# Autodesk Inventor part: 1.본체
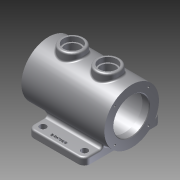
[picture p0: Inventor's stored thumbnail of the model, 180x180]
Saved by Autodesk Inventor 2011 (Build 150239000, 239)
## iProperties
Created: 2014-12
Part Number: 1.본체
Document SubType Name: Modeling
Designer: user
Density: 1 g/cm^3
Mass: 477.297 g
Surface Area: 1040.31 cm^2
Volume: 477.297 cm^3
Author: user
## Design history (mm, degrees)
sketch "스케치1"
  geometry: L1 (-47.5, 65)-(47.5, 65); L2 (47.5, 65)-(47.5, -65); L3 (47.5, -65)-(-47.5, -65); L4 (-47.5, -65)-(-47.5, 65); 3 further points
  constraints: 8 end point, 2 midpoint, 2 parallel, 1 horizontal, 1 horizontal alignment, 1 perpendicular, 1 vertical alignment
  dimensions: "d0" = 95 distance of L1.start L1.end; "d1" = 130 distance of L3.end L1.start
extrude "돌출1" new body sketch "스케치1" distance "d2" = 12; taper "d3" = 0 deg
node "작업 평면1"
sketch "스케치2"
  geometry: L1 (0, 130)-(0, 0) reference; C1 r 46 at (-50, 65); 1 further point
  constraints: 1 centre point, 1 horizontal alignment
  dimensions: "d5" = 92 diameter of C1; "d6" = 50 distance from line of L1 C1.centre
extrude "돌출2" join sketch "스케치2" distance "d7" = 140; taper "d8" = 0 deg
sketch "스케치3"
  geometry: L1 (-47.5, 4)-(-62.5, 4) reference; L2 (-62.5, 4)-(-62.5, 96) reference; L3 (-62.5, 96)-(77.5, 96) reference; L4 (77.5, 96)-(77.5, 4) reference; L5 (77.5, 4)-(47.5, 4) reference; L6 (47.5, 4)-(47.5, 0) reference; L7 (47.5, 0)-(-47.5, 0) reference; L8 (-47.5, 0)-(-47.5, 4) reference; L9 (77.5, 50)-(-62.5, 50); L10 (77.5, 80)-(65.5, 80); L11 (65.5, 80)-(65.5, 87.5); L12 (65.5, 87.5)-(-50.5, 87.5); L13 (-50.5, 87.5)-(-50.5, 80); L14 (-50.5, 80)-(-62.5, 80); 1 further point
  constraints: 12 end point, 3 parallel, 3 perpendicular, 2 midpoint, 2 point on line, 1 collinear
  dimensions: "d9" = 50 distance between parallel lines of L7 L9; "d10" = 60 diameter of L10 L9; "d11" = 60 diameter of L14 L9; "d12" = 75 diameter of L12 L9; "d13" = 12 distance of L10.start L10.end
revolve "회전1" sketch "스케치3" stored, may be unused: angle "d14" = 90 deg
sketch "스케치4"
  geometry: L1 (0, 0)-(0, 71.958); L2 (0, 0)-(-56.569, 56.569); C1 r 30 at (0, 0) reference; C2 r 46 at (0, 0) reference; 2 further points
  constraints: 4 end point, 1 midpoint, 1 vertical
  dimensions: "d16" = 45 deg angle of L1 L2; "d17" = 40 distance of C1.centre point (-28.284, 28.284)
hole "Hole1" sketch "스케치4" at (-28.284, 28.284) diameter "d18" = 3.242; stored, may be unused: countersink angle "d22" = 90 deg, drill point angle "d24" = 118 deg; dims "d19" = 8, "d20" = 4, "d21" = 2, "d23" = 10
sketch "스케치5"
  geometry: L1 (0, 0)-(0, -75.038); L2 (0, 0)-(50.786, -50.786); C1 r 30 at (0, 0) reference; C2 r 46 at (0, 0) reference; 2 further points
  constraints: 4 end point, 1 point on line, 1 vertical
  dimensions: "d28" = 45 deg angle of L1 L2; "d29" = 40 distance of C1.centre point (28.284, -28.284)
hole "Hole2" sketch "스케치5" at (28.284, -28.284) diameter "d30" = 3.242; stored, may be unused: countersink angle "d34" = 90 deg, drill point angle "d36" = 118 deg; dims "d31" = 8, "d32" = 4, "d33" = 2, "d35" = 10
node "작업 평면2"
sketch "스케치6"
  geometry: L1 (-37.5, 0)-(22.5, 0); L2 (-77.5, -46)-(-77.5, 46) reference; C1 r 20 at (-37.5, 0); C2 r 20 at (22.5, 0); 1 further point
  constraints: 2 centre point, 2 end point, 1 equal radius, 1 horizontal
  dimensions: "d41" = 60 distance of L1.start L1.end; "d42" = 40 diameter of C1; "d43" = 40 distance from line of L2 L1.start; "d44" = 46 vertical distance of L2.start L1.start
extrude "돌출3" join sketch "스케치6" stored distance "d45" = 8; taper "d46" = 0 deg
sketch "스케치7"
  geometry: C1 r 20 at (0, 0) reference; C2 r 15 at (0, 0); 1 further point
  constraints: 1 centre point, 1 coincident
  dimensions: "d47" = 30 diameter of C2
extrude "돌출4" cut sketch "스케치7" distance "d48" = 8; taper "d49" = 0 deg
sketch "스케치8"
  geometry: C1 r 15 at (0, 0) reference; C2 r 12.5 at (0, 0); 1 further point
  constraints: 1 centre point, 1 coincident
  dimensions: "d50" = 25 diameter of C2
extrude "돌출5" cut sketch "스케치8" stored distance "d51" = 8; taper "d52" = 0 deg
sketch "스케치9"
  geometry: C1 r 20 at (0, 0) reference; C2 r 15 at (0, 0); 1 further point
  constraints: 1 centre point, 1 coincident
  dimensions: "d53" = 30 diameter of C2
extrude "돌출6" cut sketch "스케치9" distance "d54" = 8; taper "d55" = 0 deg
sketch "스케치10"
  geometry: C1 r 15 at (0, 0) reference; C2 r 12.5 at (0, 0); 1 further point
  constraints: 1 centre point, 1 coincident
  dimensions: "d56" = 25 diameter of C2
extrude "돌출7" cut sketch "스케치10" stored distance "d57" = 8; taper "d58" = 0 deg
fillet "모깎기1" dims "d59" = 10
fillet "모깎기2" dims "d64" = 5
fillet "모깎기3" dims "d65" = 3
fillet "모깎기4" dims "d66" = 3
fillet "모깎기5" dims "d67" = 3
chamfer "모따기1" distance "d68" = 1; stored, may be unused: second distance "d69" = 2, angle "d70" = 45 deg
fillet "모깎기6" dims "d71" = 3
sketch "스케치12"
  geometry: L1 (-16.76, -55.098)-(10.877, -55.098); L2 (10.877, -55.098)-(10.877, -58.902); L3 (10.877, -58.902)-(-16.76, -58.902); L4 (-16.76, -58.902)-(-16.76, -55.098); L5 (-15.877, -55.098)-(10.877, -58.902); L6 (-37.5, -65)-(37.5, -65) reference; C1 r 5.5 at (-37.5, -55) reference; 2 further points
  constraints: 2 end point, 1 midpoint, 1 point on line, 2 other
  dimensions: "d72" = 35 horizontal distance of C1.centre point (-2.5, -57); "d73" = 8 distance from line of L6 point (-2.5, -57)
feature "엠보싱1" sketch "스케치12" dims "d0" = 95, "d1" = 130, "d9" = 50, "d10" = 60, "d11" = 60, "d12" = 75, "d13" = 12, "d74" = 1, "d75" = 0
chamfer "모따기2" distance "d76" = 1; stored, may be unused: second distance "d77" = 2, angle "d78" = 45 deg
sketch "스케치13"
  geometry: L1 (47.5, -55)-(47.5, -38.884) reference; L2 (-47.5, -38.884)-(-47.5, -55) reference; L3 (-37.5, -65)-(37.5, -65) reference; C1 r 5.5 at (-35, -52); C2 r 5.5 at (35, -52); 1 further point
  constraints: 2 centre point
  dimensions: "d79" = 11 diameter of C1; "d80" = 11 diameter of C2; "d81" = 12.5 distance from line of L1 C2.centre; "d82" = 12.5 distance from line of L2 C1.centre; "d83" = 70 distance of C2.centre C1.centre; "d84" = 13 distance from line of L3 C1.centre
extrude "돌출9" cut sketch "스케치13" stored distance "d85" = 10; taper "d86" = 0 deg
node "솔리드1"
pattern_circular "원형 패턴1" dims angle "d26" = 360 deg
pattern_circular "원형 패턴2" dims angle "d38" = 360 deg
mirror "대칭2"
node "절단 모서리 투영1"
other parameters: "d4" = 15, "d40" = -106
